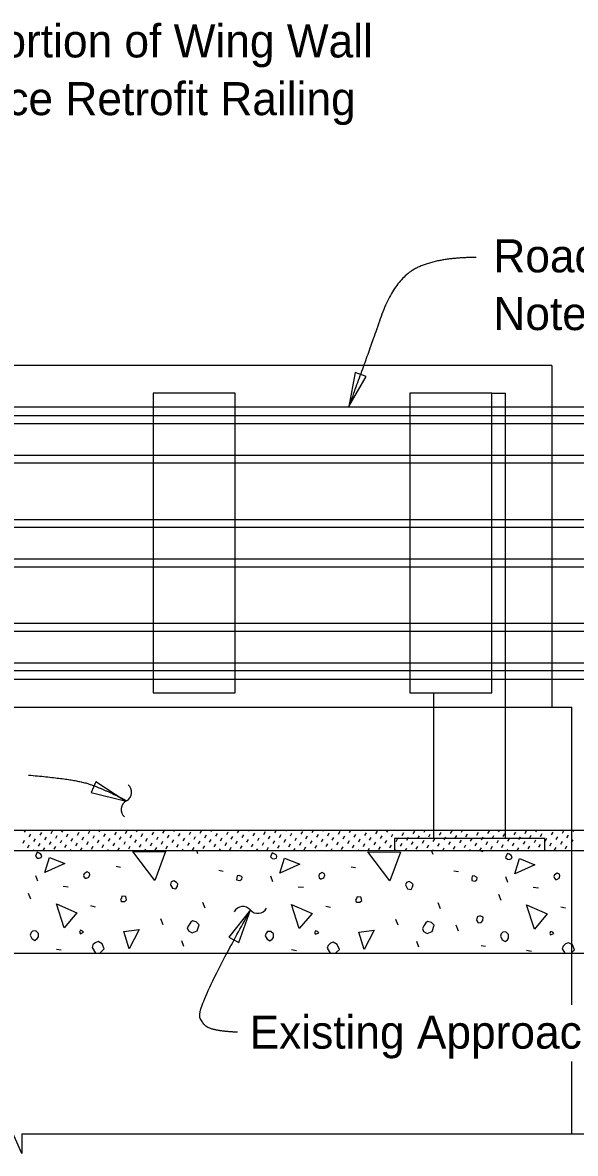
# Model space of a CAD drawing. Extents: x 2.6 to 35.7, y 1.7 to 23.4.
# Drawn here: x 14.23 to 17.6, y 5.94 to 12.84 of the extents above; entities that cross this region are included whole.
import ezdxf

# ---------------------------------------------------------------- set-up
doc = ezdxf.new("R2010")
doc.units = 0
for name, color, linetype in [('Dimension', 7, 'Continuous'), ('Miscellaneous', 7, 'Continuous'), ('TextStructures', 7, 'Continuous'), ('TrafBarrierConc', 7, 'Continuous')]:
    doc.layers.add(name, color=color, linetype=linetype)

msp = doc.modelspace()

# ---------------------------------------------------------------- linework, layer by layer
at = {"layer": 'Dimension'}
for points in [[(16.2201, 10.4968), (16.3256, 10.6799), (16.2594, 10.7044)], [(14.8563, 8.0914), (14.6802, 8.2079), (14.6516, 8.1434)], [(15.6214, 7.4265), (15.4893, 7.2616), (15.551, 7.2273)]]:
    msp.add_lwpolyline(points, close=True, dxfattribs=at)
msp.add_lwpolyline([(17.7044, 6.0586), (14.2297, 6.0586), (14.2297, 5.9424), (14.1304, 6.1674), (14.1304, 6.0586), (12.6311, 6.0586)], dxfattribs=at)
for centre, start, end in [((14.8382, 8.145), 297.39149, 49.11871), ((14.893, 8.0391), 117.39149, 229.11871), ((15.5753, 7.3876), 40.61676, 152.34398), ((15.6658, 7.4652), 220.61676, 332.34398)]:
    msp.add_arc(centre, 0.0596, start, end, dxfattribs=at)
for points in [[(16.9954, 11.4048), (16.7489, 11.4048), (16.4916, 11.2618), (16.338, 10.815), (16.2201, 10.4969)], [(14.2692, 8.249), (14.5358, 8.2258), (14.7118, 8.1722), (14.8653, 8.0941)], [(15.543, 6.6805), (15.4302, 6.6867), (15.3299, 6.7181), (15.2955, 6.8403), (15.6214, 7.4265)]]:
    msp.add_open_spline(points, degree=2, dxfattribs=at)
at = {"layer": 'Miscellaneous'}
for p, q in [((17.0915, 10.5767), (17.1748, 10.5767)), ((17.1748, 7.8613), (17.1748, 10.5767)), ((10.4769, 10.4934), (17.9962, 10.4934)), ((11.1345, 10.4413), (17.9962, 10.4413)), ((11.1357, 10.393), (17.9962, 10.393)), ((11.1404, 10.2002), (17.9962, 10.2002)), ((11.1416, 10.152), (17.9962, 10.152)), ((11.1381, 9.808), (17.9962, 9.808)), ((11.1369, 9.7598), (17.9962, 9.7598)), ((11.1309, 9.5189), (17.9962, 9.5189)), ((11.1321, 9.567), (17.9962, 9.567)), ((11.1416, 9.1749), (17.9962, 9.1749)), ((11.1404, 9.1267), (17.9962, 9.1267)), ((11.1357, 8.9339), (17.9962, 8.9339)), ((10.4769, 8.8333), (17.9962, 8.8333)), ((11.1345, 8.8856), (17.9962, 8.8856)), ((16.7373, 7.8613), (16.7373, 8.75)), ((14.2461, 7.9007), (14.2534, 7.9134)), ((14.2744, 7.8725), (14.2841, 7.8893)), ((14.3027, 7.8442), (14.3124, 7.861)), ((14.3124, 7.9105), (14.3141, 7.9134)), ((14.3407, 7.8822), (14.3504, 7.899)), ((14.369, 7.8539), (14.3787, 7.8707)), ((14.407, 7.8919), (14.4167, 7.9087)), ((14.4353, 7.8636), (14.445, 7.8804)), ((14.4733, 7.9016), (14.4801, 7.9134)), ((14.5015, 7.8733), (14.5113, 7.8901)), ((14.5298, 7.8451), (14.5396, 7.8619)), ((14.5396, 7.9113), (14.5407, 7.9134)), ((14.5678, 7.8831), (14.5776, 7.8999)), ((14.5961, 7.8548), (14.6058, 7.8716)), ((14.6341, 7.8928), (14.6439, 7.9096)), ((14.6624, 7.8645), (14.6721, 7.8813)), ((14.7004, 7.9025), (14.7067, 7.9134)), ((14.7287, 7.8742), (14.7384, 7.891)), ((14.757, 7.8459), (14.7667, 7.8627)), ((14.7667, 7.9122), (14.7674, 7.9134)), ((14.795, 7.8839), (14.8047, 7.9007)), ((14.8233, 7.8557), (14.833, 7.8725)), ((14.8613, 7.8937), (14.871, 7.9105)), ((14.8896, 7.8654), (14.8993, 7.8822)), ((14.9276, 7.9034), (14.9334, 7.9134)), ((14.9559, 7.8751), (14.9656, 7.8919)), ((14.9841, 7.8468), (14.9939, 7.8636)), ((14.9939, 7.9131), (14.994, 7.9134)), ((15.0222, 7.8848), (15.0319, 7.9016)), ((15.0504, 7.8565), (15.0602, 7.8733)), ((15.0884, 7.8946), (15.0982, 7.9113)), ((15.1167, 7.8663), (15.1265, 7.8831)), ((15.1547, 7.9043), (15.16, 7.9134)), ((15.183, 7.876), (15.1927, 7.8928)), ((15.2113, 7.8477), (15.221, 7.8645)), ((15.2493, 7.8857), (15.259, 7.9025)), ((15.2776, 7.8574), (15.2873, 7.8742)), ((15.3156, 7.8954), (15.3253, 7.9122)), ((15.3439, 7.8672), (15.3536, 7.8839)), ((15.3819, 7.9052), (15.3867, 7.9134)), ((15.4102, 7.8769), (15.4199, 7.8937)), ((15.4385, 7.8486), (15.4482, 7.8654)), ((15.4765, 7.8866), (15.4862, 7.9034)), ((15.5048, 7.8583), (15.5145, 7.8751)), ((15.5428, 7.8963), (15.5525, 7.9131)), ((15.571, 7.868), (15.5808, 7.8848)), ((15.6091, 7.906), (15.6133, 7.9134)), ((15.6373, 7.8778), (15.6471, 7.8946)), ((15.6656, 7.8495), (15.6753, 7.8663)), ((15.7036, 7.8875), (15.7134, 7.9043)), ((15.7319, 7.8592), (15.7416, 7.876)), ((15.7699, 7.8972), (15.7793, 7.9134)), ((15.7982, 7.8689), (15.8079, 7.8857)), ((15.8362, 7.9069), (15.84, 7.9134)), ((15.8645, 7.8786), (15.8742, 7.8954)), ((15.8928, 7.8504), (15.9025, 7.8672)), ((15.9308, 7.8884), (15.9405, 7.9052)), ((15.9591, 7.8601), (15.9688, 7.8769)), ((15.9971, 7.8981), (16.0059, 7.9134)), ((16.0254, 7.8698), (16.0351, 7.8866)), ((16.0634, 7.9078), (16.0666, 7.9134)), ((16.0917, 7.8795), (16.1014, 7.8963)), ((16.1199, 7.8512), (16.1297, 7.868)), ((16.1579, 7.8893), (16.1677, 7.906)), ((16.1862, 7.861), (16.196, 7.8778)), ((16.2242, 7.899), (16.2326, 7.9134)), ((16.2525, 7.8707), (16.2622, 7.8875)), ((16.2905, 7.9087), (16.2933, 7.9134)), ((16.3188, 7.8804), (16.3285, 7.8972)), ((16.3471, 7.8521), (16.3568, 7.8689)), ((16.3851, 7.8901), (16.3948, 7.9069)), ((16.4134, 7.8619), (16.4231, 7.8786)), ((16.4514, 7.8999), (16.4592, 7.9134)), ((16.4797, 7.8716), (16.4894, 7.8884)), ((16.508, 7.8433), (16.5177, 7.8601)), ((16.5177, 7.9096), (16.5199, 7.9134)), ((16.546, 7.8813), (16.5557, 7.8981)), ((16.5743, 7.853), (16.584, 7.8698)), ((16.6123, 7.891), (16.622, 7.9078)), ((16.6405, 7.8627), (16.6503, 7.8795)), ((16.6786, 7.9007), (16.6859, 7.9134)), ((16.7068, 7.8725), (16.7166, 7.8893)), ((16.7351, 7.8442), (16.7448, 7.861)), ((16.7448, 7.9105), (16.7465, 7.9134)), ((16.7731, 7.8822), (16.7829, 7.899)), ((16.8014, 7.8539), (16.8111, 7.8707)), ((16.8394, 7.8919), (16.8491, 7.9087)), ((16.8677, 7.8636), (16.8774, 7.8804)), ((16.9057, 7.9016), (16.9125, 7.9134)), ((16.934, 7.8733), (16.9437, 7.8901)), ((16.9623, 7.8451), (16.972, 7.8619)), ((16.972, 7.9113), (16.9732, 7.9134)), ((17.0003, 7.8831), (17.01, 7.8999)), ((17.0286, 7.8548), (17.0383, 7.8716)), ((17.0666, 7.8928), (17.0763, 7.9096)), ((17.0949, 7.8645), (17.1046, 7.8813)), ((17.1329, 7.9025), (17.1392, 7.9134)), ((17.1612, 7.8742), (17.1709, 7.891)), ((17.1894, 7.8459), (17.1992, 7.8627)), ((17.1992, 7.9122), (17.1998, 7.9134)), ((17.2274, 7.8839), (17.2372, 7.9007)), ((17.2557, 7.8557), (17.2655, 7.8725)), ((17.2937, 7.8937), (17.3035, 7.9105)), ((17.322, 7.8654), (17.3317, 7.8822)), ((17.36, 7.9034), (17.3658, 7.9134)), ((17.3883, 7.8751), (17.398, 7.8919)), ((17.4166, 7.8468), (17.4263, 7.8636)), ((17.4263, 7.9131), (17.4265, 7.9134)), ((17.4546, 7.8848), (17.4643, 7.9016)), ((17.4829, 7.8565), (17.4926, 7.8733)), ((17.5209, 7.8946), (17.5306, 7.9113)), ((17.5492, 7.8663), (17.5589, 7.8831)), ((17.5872, 7.9043), (17.5925, 7.9134)), ((14.2364, 7.8345), (14.2461, 7.8512)), ((14.2647, 7.8062), (14.2744, 7.823)), ((14.299, 7.7884), (14.3027, 7.7947)), ((14.331, 7.8159), (14.3407, 7.8327)), ((14.3597, 7.7884), (14.369, 7.8044)), ((14.3973, 7.8256), (14.407, 7.8424)), ((14.4255, 7.7973), (14.4353, 7.8141)), ((14.4635, 7.8353), (14.4733, 7.8521)), ((14.4918, 7.807), (14.5015, 7.8238)), ((14.5257, 7.7884), (14.5298, 7.7956)), ((14.5581, 7.8168), (14.5678, 7.8336)), ((14.5864, 7.7885), (14.5961, 7.8053)), ((14.6244, 7.8265), (14.6341, 7.8433)), ((14.6527, 7.7982), (14.6624, 7.815)), ((14.6907, 7.8362), (14.7004, 7.853)), ((14.719, 7.8079), (14.7287, 7.8247)), ((14.7523, 7.7884), (14.757, 7.7964)), ((14.7853, 7.8177), (14.795, 7.8345)), ((14.8136, 7.7894), (14.8233, 7.8062)), ((14.8516, 7.8274), (14.8613, 7.8442)), ((14.8799, 7.7991), (14.8896, 7.8159)), ((14.9179, 7.8371), (14.9276, 7.8539)), ((14.9461, 7.8088), (14.9559, 7.8256)), ((14.979, 7.7884), (14.9841, 7.7973)), ((15.0124, 7.8185), (15.0222, 7.8353)), ((15.0407, 7.7903), (15.0504, 7.807)), ((15.0787, 7.8283), (15.0884, 7.8451)), ((15.107, 7.8), (15.1167, 7.8168)), ((15.145, 7.838), (15.1547, 7.8548)), ((15.1733, 7.8097), (15.183, 7.8265)), ((15.2056, 7.7884), (15.2113, 7.7982)), ((15.2396, 7.8194), (15.2493, 7.8362)), ((15.2679, 7.7911), (15.2776, 7.8079)), ((15.3059, 7.8291), (15.3156, 7.8459)), ((15.3342, 7.8009), (15.3439, 7.8177)), ((15.3722, 7.8389), (15.3819, 7.8557)), ((15.4005, 7.8106), (15.4102, 7.8274)), ((15.4323, 7.7884), (15.4385, 7.7991)), ((15.4667, 7.8203), (15.4765, 7.8371)), ((15.495, 7.792), (15.5048, 7.8088)), ((15.533, 7.83), (15.5428, 7.8468)), ((15.5613, 7.8017), (15.571, 7.8185)), ((15.5993, 7.8398), (15.6091, 7.8565)), ((15.6276, 7.8115), (15.6373, 7.8283)), ((15.6589, 7.7884), (15.6656, 7.8)), ((15.6939, 7.8212), (15.7036, 7.838)), ((15.7222, 7.7929), (15.7319, 7.8097)), ((15.7602, 7.8309), (15.7699, 7.8477)), ((15.7885, 7.8026), (15.7982, 7.8194)), ((15.8249, 7.7884), (15.8265, 7.7911)), ((15.8265, 7.8406), (15.8362, 7.8574)), ((15.8548, 7.8124), (15.8645, 7.8291)), ((15.8856, 7.7884), (15.8928, 7.8009)), ((15.9211, 7.8221), (15.9308, 7.8389)), ((15.9493, 7.7938), (15.9591, 7.8106)), ((15.9874, 7.8318), (15.9971, 7.8486)), ((16.0156, 7.8035), (16.0254, 7.8203)), ((16.0516, 7.7884), (16.0536, 7.792)), ((16.0536, 7.8415), (16.0634, 7.8583)), ((16.0819, 7.8132), (16.0917, 7.83)), ((16.1122, 7.7884), (16.1199, 7.8017)), ((16.1482, 7.823), (16.1579, 7.8398)), ((16.1765, 7.7947), (16.1862, 7.8115)), ((16.2145, 7.8327), (16.2242, 7.8495)), ((16.2428, 7.8044), (16.2525, 7.8212)), ((16.2782, 7.7884), (16.2808, 7.7929)), ((16.2808, 7.8424), (16.2905, 7.8592)), ((16.3091, 7.8141), (16.3188, 7.8309)), ((16.3389, 7.7884), (16.3471, 7.8026)), ((16.3754, 7.8238), (16.3851, 7.8406)), ((16.4037, 7.7956), (16.4134, 7.8124)), ((16.4417, 7.8336), (16.4514, 7.8504)), ((16.47, 7.8053), (16.4797, 7.8221)), ((16.5048, 7.7884), (16.508, 7.7938)), ((16.5362, 7.815), (16.546, 7.8318)), ((16.5655, 7.7884), (16.5743, 7.8035)), ((16.6025, 7.8247), (16.6123, 7.8415)), ((16.6308, 7.7964), (16.6405, 7.8132)), ((16.6688, 7.8345), (16.6786, 7.8512)), ((16.6971, 7.8062), (16.7068, 7.823)), ((16.7315, 7.7884), (16.7351, 7.7947)), ((16.7634, 7.8159), (16.7731, 7.8327)), ((16.7922, 7.7884), (16.8014, 7.8044)), ((16.8297, 7.8256), (16.8394, 7.8424)), ((16.858, 7.7973), (16.8677, 7.8141)), ((16.896, 7.8353), (16.9057, 7.8521)), ((16.9243, 7.807), (16.934, 7.8238)), ((16.9581, 7.7884), (16.9623, 7.7956)), ((16.9906, 7.8168), (17.0003, 7.8336)), ((17.0188, 7.7885), (17.0286, 7.8053)), ((17.0569, 7.8265), (17.0666, 7.8433)), ((17.0851, 7.7982), (17.0949, 7.815)), ((17.1231, 7.8362), (17.1329, 7.853)), ((17.1514, 7.8079), (17.1612, 7.8247)), ((17.1848, 7.7884), (17.1894, 7.7964)), ((17.2177, 7.8177), (17.2274, 7.8345)), ((17.246, 7.7894), (17.2557, 7.8062)), ((17.284, 7.8274), (17.2937, 7.8442)), ((17.3123, 7.7991), (17.322, 7.8159)), ((17.3503, 7.8371), (17.36, 7.8539)), ((17.3786, 7.8088), (17.3883, 7.8256)), ((17.4114, 7.7884), (17.4166, 7.7973)), ((17.4449, 7.8185), (17.4546, 7.8353)), ((17.4732, 7.7903), (17.4829, 7.807)), ((17.5112, 7.8283), (17.5209, 7.8451)), ((17.5395, 7.8), (17.5492, 7.8168)), ((17.5775, 7.838), (17.5872, 7.8548)), ((15.145, 7.7884), (15.145, 7.7885)), ((15.3018, 7.768), (15.2943, 7.7884)), ((15.3716, 7.7884), (15.3722, 7.7894)), ((15.5983, 7.7884), (15.5993, 7.7903)), ((15.6001, 7.7884), (15.6041, 7.7874)), ((16.7337, 7.7644), (16.7249, 7.7884)), ((17.0179, 7.7884), (17.036, 7.7839)), ((17.5774, 7.7884), (17.5775, 7.7885)), ((14.8033, 7.6937), (14.8298, 7.6884)), ((15.4291, 7.669), (15.4556, 7.6637)), ((16.2352, 7.6902), (16.2617, 7.6849)), ((16.861, 7.6654), (16.8875, 7.6601)), ((14.326, 7.6018), (14.3136, 7.6354)), ((15.7579, 7.5983), (15.7455, 7.6319)), ((17.1898, 7.5947), (17.1774, 7.6283)), ((14.2836, 7.4922), (14.2694, 7.5276)), ((14.4798, 7.5718), (14.5116, 7.5682)), ((15.9117, 7.5682), (15.9435, 7.5647)), ((17.1473, 7.4851), (17.1332, 7.5205)), ((17.3436, 7.5647), (17.3754, 7.5611)), ((14.6477, 7.4533), (14.676, 7.4462)), ((15.346, 7.4374), (15.3318, 7.4728)), ((16.0796, 7.4498), (16.1079, 7.4427)), ((16.7779, 7.4339), (16.7637, 7.4692)), ((17.5115, 7.4462), (17.5398, 7.4392)), ((15.0897, 7.3366), (15.0755, 7.372)), ((16.5216, 7.3331), (16.5074, 7.3685)), ((16.8892, 7.2977), (16.8751, 7.3331)), ((14.4391, 7.1881), (14.4692, 7.1828)), ((15.2152, 7.2041), (15.2028, 7.2376)), ((15.871, 7.1846), (15.9011, 7.1793)), ((16.6471, 7.2005), (16.6347, 7.2341)), ((17.0271, 7.2094), (17.0519, 7.2058)), ((17.3029, 7.1811), (17.333, 7.1758))]:
    msp.add_line(p, q, dxfattribs=at)
for points in [[(15.029, 8.75), (15.529, 8.75), (15.529, 10.5767), (15.029, 10.5767)], [(16.5915, 8.75), (17.0915, 8.75), (17.0915, 10.5767), (16.5915, 10.5767)], [(16.4978, 7.7884), (17.4144, 7.7884), (17.4144, 7.8613), (16.4978, 7.8613)]]:
    msp.add_lwpolyline(points, close=True, dxfattribs=at)
for points in [[(14.3225, 7.7432), (14.3348, 7.7415), (14.3472, 7.7468), (14.3507, 7.7574), (14.3454, 7.7662), (14.3348, 7.7733), (14.3225, 7.7786), (14.3154, 7.7644), (14.3118, 7.7538), (14.3225, 7.7432)], [(14.3684, 7.6548), (14.3967, 7.7468), (14.4904, 7.7096), (14.3684, 7.6548)], [(15.0384, 7.6071), (14.904, 7.7839), (15.1038, 7.7821), (15.0384, 7.6071)], [(15.7543, 7.7397), (15.7667, 7.7379), (15.7791, 7.7432), (15.7826, 7.7538), (15.7773, 7.7627), (15.7667, 7.7697), (15.7543, 7.775), (15.7473, 7.7609), (15.7437, 7.7503), (15.7543, 7.7397)], [(15.8003, 7.6513), (15.8286, 7.7432), (15.9223, 7.7061), (15.8003, 7.6513)], [(16.4703, 7.6036), (16.3359, 7.7803), (16.5357, 7.7786), (16.4703, 7.6036)], [(17.1862, 7.7362), (17.1986, 7.7344), (17.211, 7.7397), (17.2145, 7.7503), (17.2092, 7.7591), (17.1986, 7.7662), (17.1862, 7.7715), (17.1792, 7.7574), (17.1756, 7.7468), (17.1862, 7.7362)], [(17.2322, 7.6478), (17.2605, 7.7397), (17.3542, 7.7026), (17.2322, 7.6478)], [(14.6159, 7.6195), (14.623, 7.6195), (14.6371, 7.6266), (14.6424, 7.6425), (14.6407, 7.6513), (14.6265, 7.6584), (14.6088, 7.6478), (14.6053, 7.6372), (14.6088, 7.6266), (14.6159, 7.6195)], [(16.0478, 7.6159), (16.0549, 7.6159), (16.069, 7.623), (16.0743, 7.6389), (16.0725, 7.6478), (16.0584, 7.6548), (16.0407, 7.6442), (16.0372, 7.6336), (16.0407, 7.623), (16.0478, 7.6159)], [(15.1374, 7.5753), (15.1462, 7.5594), (15.1674, 7.5558), (15.1763, 7.5718), (15.1798, 7.5859), (15.171, 7.5947), (15.1551, 7.6036), (15.1392, 7.5983), (15.1339, 7.5824), (15.1374, 7.5753)], [(15.5369, 7.6106), (15.5564, 7.6053), (15.5687, 7.6142), (15.5705, 7.6266), (15.567, 7.6301), (15.5528, 7.6372), (15.5404, 7.6354), (15.5387, 7.623), (15.5369, 7.6106)], [(16.5693, 7.5718), (16.5781, 7.5558), (16.5993, 7.5523), (16.6082, 7.5682), (16.6117, 7.5824), (16.6029, 7.5912), (16.587, 7.6), (16.5711, 7.5947), (16.5657, 7.5788), (16.5693, 7.5718)], [(16.9688, 7.6071), (16.9882, 7.6018), (17.0006, 7.6106), (17.0024, 7.623), (16.9989, 7.6266), (16.9847, 7.6336), (16.9723, 7.6319), (16.9706, 7.6195), (16.9688, 7.6071)], [(17.4797, 7.6124), (17.4868, 7.6124), (17.5009, 7.6195), (17.5062, 7.6354), (17.5044, 7.6442), (17.4903, 7.6513), (17.4726, 7.6407), (17.4691, 7.6301), (17.4726, 7.6195), (17.4797, 7.6124)], [(14.4869, 7.3172), (14.4391, 7.4639), (14.5646, 7.4091), (14.4869, 7.3172)], [(14.8351, 7.4781), (14.8563, 7.4781), (14.8669, 7.4887), (14.8616, 7.5081), (14.8386, 7.5099), (14.8351, 7.4993), (14.8298, 7.4904), (14.8351, 7.4781), (14.8316, 7.4816)], [(15.9187, 7.3137), (15.871, 7.4604), (15.9965, 7.4056), (15.9187, 7.3137)], [(16.267, 7.4745), (16.2882, 7.4745), (16.2988, 7.4851), (16.2935, 7.5046), (16.2705, 7.5063), (16.267, 7.4957), (16.2617, 7.4869), (16.267, 7.4745), (16.2635, 7.4781)], [(17.3506, 7.3101), (17.3029, 7.4568), (17.4284, 7.402), (17.3506, 7.3101)], [(16.9989, 7.3649), (17.0077, 7.349), (17.0271, 7.3508), (17.036, 7.3632), (17.0377, 7.3826), (17.0254, 7.3879), (17.0165, 7.3897), (17.0059, 7.3861), (17.0024, 7.3826), (16.9989, 7.3649)], [(15.2435, 7.2995), (15.2664, 7.2871), (15.2965, 7.2995), (15.3089, 7.3366), (15.2912, 7.3543), (15.2682, 7.3596), (15.2576, 7.3525), (15.2452, 7.3331), (15.2364, 7.3172), (15.2435, 7.2995)], [(16.6754, 7.296), (16.6983, 7.2836), (16.7284, 7.296), (16.7408, 7.3331), (16.7231, 7.3508), (16.7001, 7.3561), (16.6895, 7.349), (16.6771, 7.3296), (16.6683, 7.3137), (16.6754, 7.296)], [(14.28, 7.273), (14.2906, 7.2518), (14.3083, 7.2412), (14.3225, 7.2518), (14.3295, 7.2624), (14.3295, 7.2836), (14.3136, 7.2995), (14.2942, 7.2977), (14.2853, 7.2889), (14.28, 7.273)], [(14.5858, 7.2818), (14.6053, 7.2907), (14.5982, 7.2977), (14.5858, 7.3031), (14.5805, 7.2907), (14.5858, 7.2818)], [(14.8828, 7.1899), (14.8492, 7.2942), (14.9429, 7.3066), (14.8828, 7.1899)], [(15.7119, 7.2695), (15.7225, 7.2483), (15.7402, 7.2376), (15.7543, 7.2483), (15.7614, 7.2589), (15.7614, 7.2801), (15.7455, 7.296), (15.7261, 7.2942), (15.7172, 7.2854), (15.7119, 7.2695)], [(16.0177, 7.2783), (16.0372, 7.2871), (16.0301, 7.2942), (16.0177, 7.2995), (16.0124, 7.2871), (16.0177, 7.2783)], [(16.3147, 7.1864), (16.2811, 7.2907), (16.3748, 7.3031), (16.3147, 7.1864)], [(17.1438, 7.2659), (17.1544, 7.2447), (17.1721, 7.2341), (17.1862, 7.2447), (17.1933, 7.2553), (17.1933, 7.2765), (17.1774, 7.2924), (17.158, 7.2907), (17.1491, 7.2818), (17.1438, 7.2659)], [(17.4496, 7.2748), (17.4691, 7.2836), (17.462, 7.2907), (17.4496, 7.296), (17.4443, 7.2836), (17.4496, 7.2748)], [(14.7043, 7.1634), (14.7114, 7.1705), (14.7308, 7.1899), (14.7184, 7.22), (14.6937, 7.2341), (14.676, 7.227), (14.6619, 7.2129), (14.6566, 7.197)], [(14.6566, 7.197), (14.6774, 7.1634)], [(16.1397, 7.1634), (16.1433, 7.1669), (16.1627, 7.1864), (16.1503, 7.2164), (16.1256, 7.2306), (16.1079, 7.2235), (16.0938, 7.2094), (16.0885, 7.1935)], [(16.0885, 7.1935), (16.1071, 7.1634)], [(17.5751, 7.1634), (17.5751, 7.1634), (17.5946, 7.1828), (17.5822, 7.2129), (17.5575, 7.227), (17.5398, 7.22), (17.5256, 7.2058), (17.5203, 7.1899)], [(17.5203, 7.1899), (17.5368, 7.1634)]]:
    msp.add_lwpolyline(points, dxfattribs=at)
at = {"layer": 'TrafBarrierConc'}
for p, q in [((17.4572, 10.7467), (8.4846, 10.7467)), ((17.4572, 10.7467), (17.4572, 8.6634)), ((8.4846, 8.6634), (17.4572, 8.6634)), ((17.4573, 8.6634), (17.5794, 8.6634)), ((17.5794, 6.8481), (17.5794, 8.6634)), ((8.4846, 7.9134), (17.9962, 7.9134)), ((8.4846, 7.7884), (17.9962, 7.7884)), ((8.4846, 7.1633), (17.9962, 7.1633)), ((17.5794, 6.0586), (17.5794, 6.5034))]:
    msp.add_line(p, q, dxfattribs=at)

# ---------------------------------------------------------------- texts
at = {"layer": 'Dimension'}
for s, p in [('Begin Flared Portion of Wing Wall', (12.3215, 12.6244)), ('and Vertical Face Retrofit Railing', (12.3215, 12.2724)), ('Roadway Guardrail Transition (See ', (17.1007, 11.3141)), ('Note 1, This Sheet & Note 1, Sheet 1)', (17.1007, 10.9621))]:
    msp.add_text(s, height=0.2016, dxfattribs=at).set_placement(p)
at = {"layer": 'TextStructures'}
msp.add_text('Existing Approach Slab', height=0.2016, dxfattribs=at).set_placement((15.6162, 6.5811))

doc.saveas('drawing.dxf')
